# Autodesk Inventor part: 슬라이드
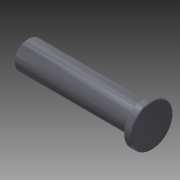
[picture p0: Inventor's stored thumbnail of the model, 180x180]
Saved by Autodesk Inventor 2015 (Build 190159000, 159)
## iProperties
Created: 2015-10
Part Number: 슬라이드
Document SubType Name: Modeling
Designer: mdu
Density: 7.86 g/cm^3
Material: 강철, 연강
Mass: 1603.27 g
Surface Area: 269.019 cm^2
Volume: 203.978 cm^3
Appearance: 강철 - 광택
Author: mdu
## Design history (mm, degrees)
sketch "스케치1"
  geometry: L1 (-75, 162)-(-75, 58) reference; L2 (-148, 110)-(22, 110); L3 (-148, 110)-(-148, 129); L4 (-148, 129)-(12, 129); L5 (12, 129)-(12, 139); L6 (12, 139)-(22, 139); L7 (22, 139)-(22, 110); 2 further points
  constraints: 12 end point, 3 parallel, 3 perpendicular, 1 midpoint, 1 point on line
  dimensions: "d0" = 58 diameter of L6 L2; "d1" = 38 diameter of L4 L2; "d2" = 10 distance of L5.end L6.end; "d3" = 170 distance of L2.start L2.end; "d4" = 73 distance between parallel lines of L3 L1
revolve "회전1" sketch "스케치1" stored, may be unused: angle "d5" = 90 deg
hole "구멍1" diameter "d11" = 13.376; stored, may be unused: countersink angle "d15" = 90 deg, drill point angle "d17" = 118 deg; dims "d9" = 10, "d10" = 10, "d12" = 22, "d13" = 4, "d14" = 2, "d16" = 25
chamfer "모따기1" distance "d6" = 1; stored, may be unused: second distance "d7" = 2, angle "d8" = 45 deg
node "솔리드1"
node "참조1"
